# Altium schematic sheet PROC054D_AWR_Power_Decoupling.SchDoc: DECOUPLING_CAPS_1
size 558 x 431 mm; Date: Not shown in title block; ApprovedBy: Not shown in title block; CheckedBy: Not shown in title block; Author: Not shown in title block; CompanyName: Not shown in title block; DrawnBy: a0271760; Engineer: Not shown in title block; Organization: Not shown in title block; Address1: Not shown in title block; Address2: Not shown in title block; Address3: Not shown in title block; Address4: Not shown in title block; DocumentNumber: 11; Revision: Use project pAWRameter SCH_Rev; SheetNumber: 11; SheetTotal: 19; PageSetup: Record=PageOptions¦CenterHorizontal=True¦CenterVertical=True¦PrintScale=1.00¦XCorrection=1.00¦YCorrection=1.00¦PrintKind=0¦BorderSize=5000000¦LeftOffset=0¦BottomOffset=0¦Orientation=2¦PaperLength=1000¦PaperWidth=1000¦Scale=100¦PaperSource=15¦PrintQuality=600¦MediaType=1¦DitherType=10¦PaperKind=Letter¦PrintScaleMode=1
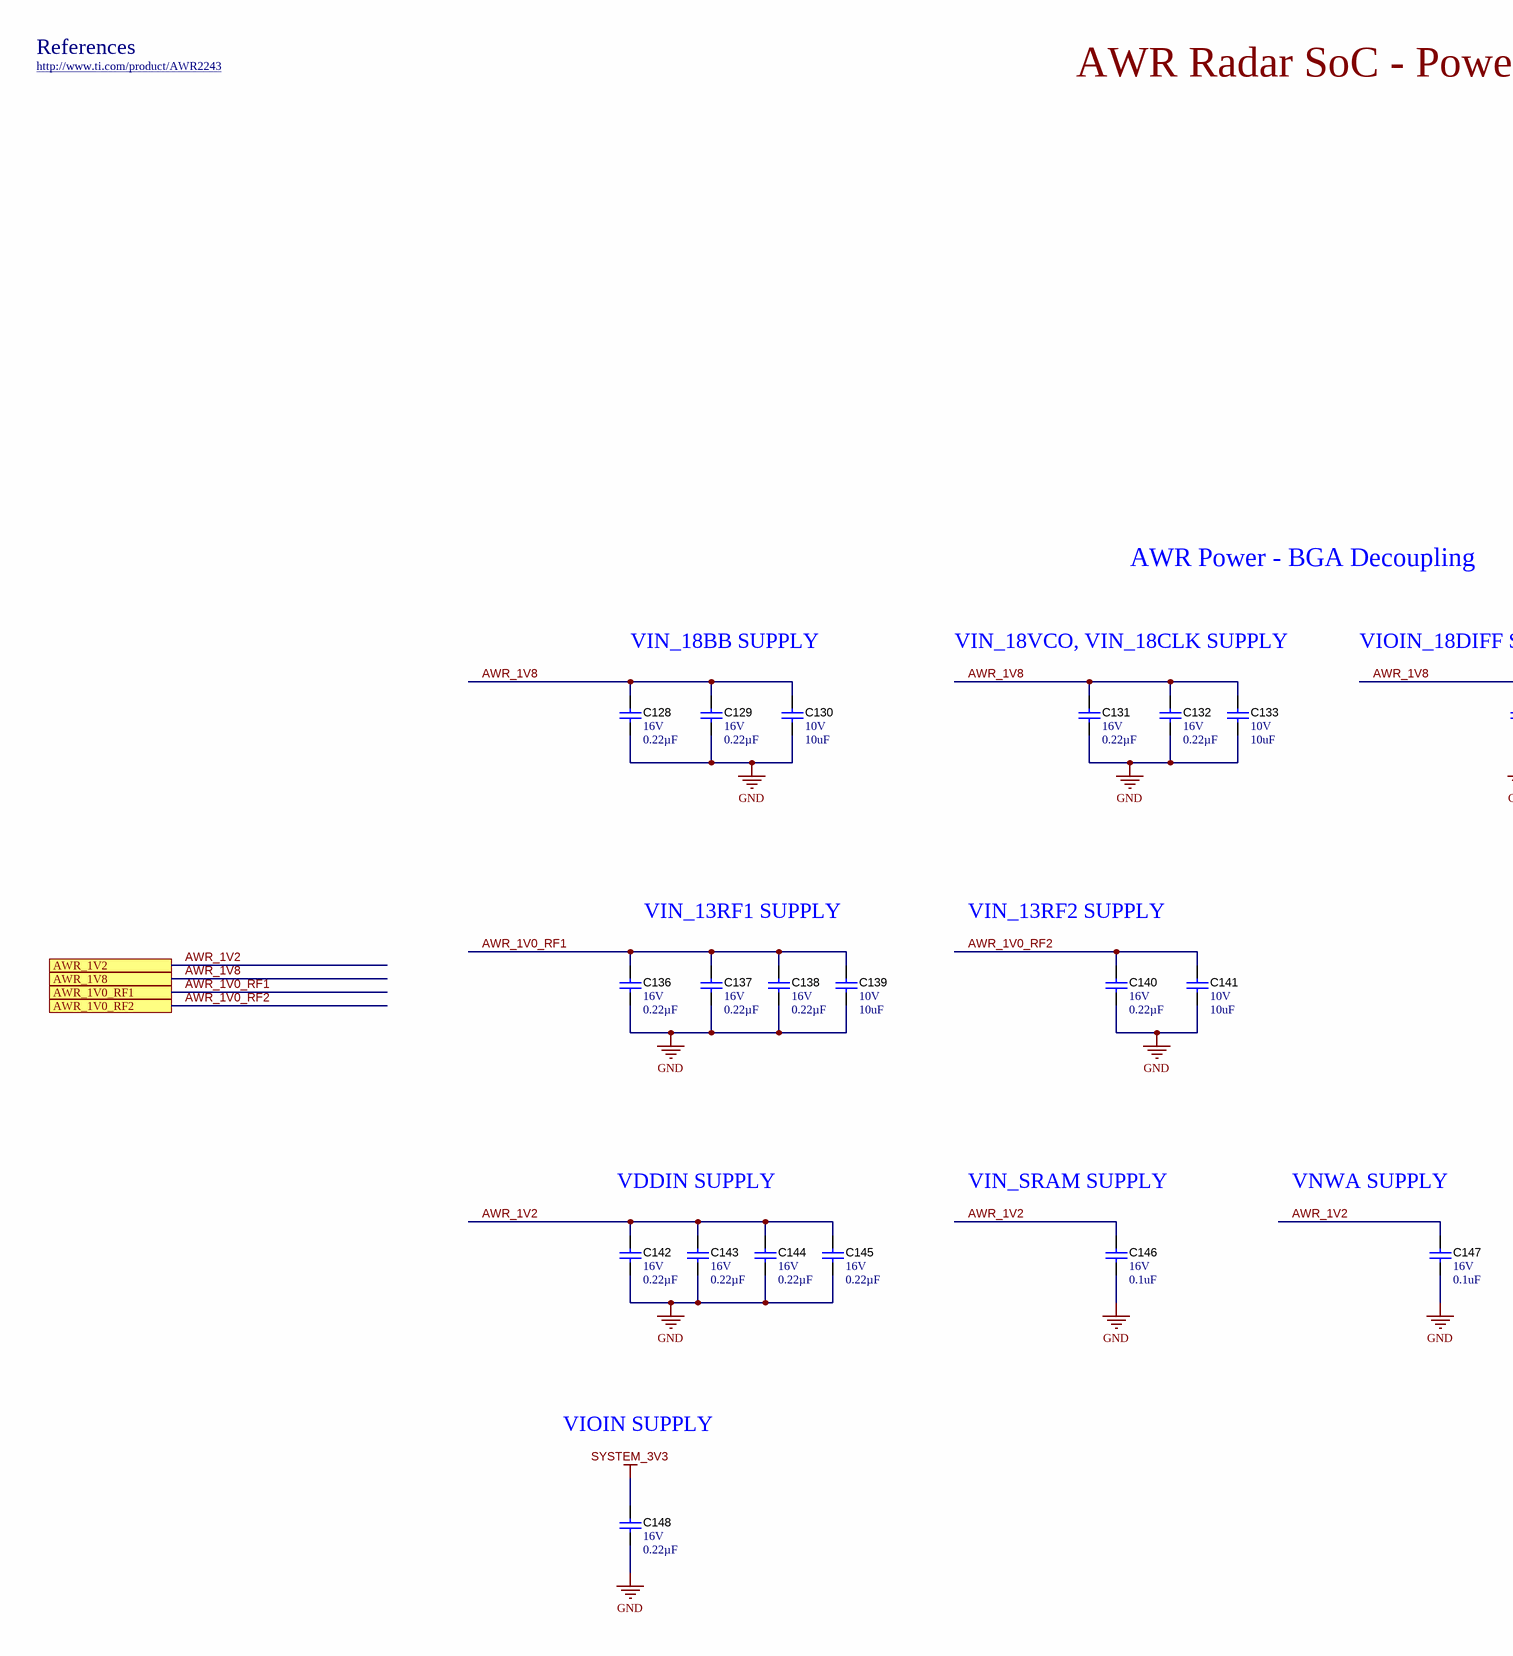
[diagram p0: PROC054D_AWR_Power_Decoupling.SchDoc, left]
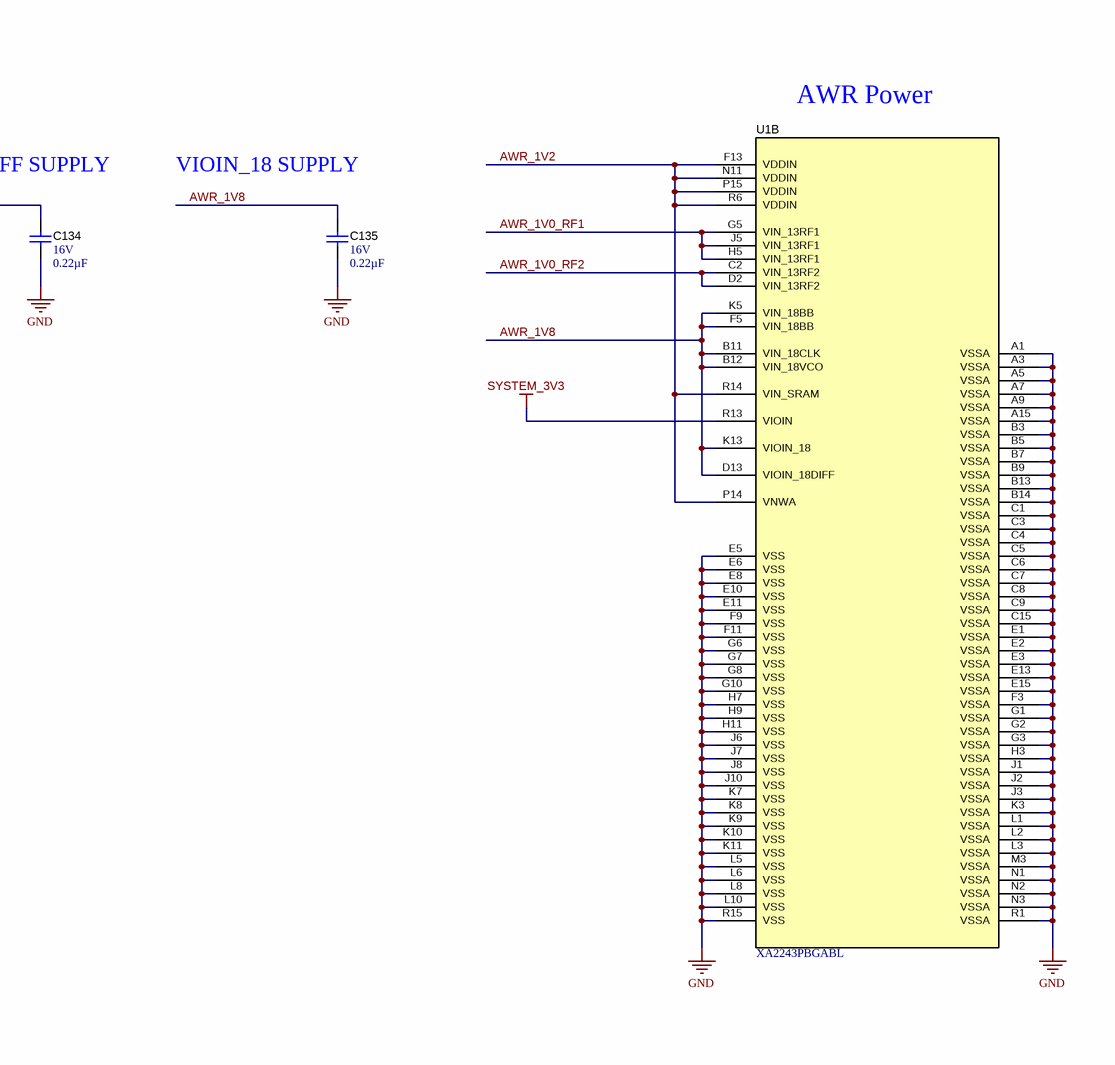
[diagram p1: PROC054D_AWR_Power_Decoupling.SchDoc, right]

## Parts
C128  VDC_V: 16V  ValueDisplayed: 0.22µF  [0402S]  (hidden comment: GCM155R71C224KE02D)
C129  VDC_V: 16V  ValueDisplayed: 0.22µF  [0402S]  (hidden comment: GCM155R71C224KE02D)
C130  VDC_V: 10V  ValueDisplayed: 10uF  [0805L]  (hidden comment: GCM21BR71A106KE22L)
C131  VDC_V: 16V  ValueDisplayed: 0.22µF  [0402S]  (hidden comment: GCM155R71C224KE02D)
C132  VDC_V: 16V  ValueDisplayed: 0.22µF  [0402S]  (hidden comment: GCM155R71C224KE02D)
C133  VDC_V: 10V  ValueDisplayed: 10uF  [0805L]  (hidden comment: GCM21BR71A106KE22L)
C134  VDC_V: 16V  ValueDisplayed: 0.22µF  [0402S]  (hidden comment: GCM155R71C224KE02D)
C135  VDC_V: 16V  ValueDisplayed: 0.22µF  [0402S]  (hidden comment: GCM155R71C224KE02D)
C136  VDC_V: 16V  ValueDisplayed: 0.22µF  [0402S]  (hidden comment: GCM155R71C224KE02D)
C137  VDC_V: 16V  ValueDisplayed: 0.22µF  [0402S]  (hidden comment: GCM155R71C224KE02D)
C138  VDC_V: 16V  ValueDisplayed: 0.22µF  [0402S]  (hidden comment: GCM155R71C224KE02D)
C139  VDC_V: 10V  ValueDisplayed: 10uF  [0805L]  (hidden comment: GCM21BR71A106KE22L)
C140  VDC_V: 16V  ValueDisplayed: 0.22µF  [0402S]  (hidden comment: GCM155R71C224KE02D)
C141  VDC_V: 10V  ValueDisplayed: 10uF  [0805L]  (hidden comment: GCM21BR71A106KE22L)
C142  VDC_V: 16V  ValueDisplayed: 0.22µF  [0402S]  (hidden comment: GCM155R71C224KE02D)
C143  VDC_V: 16V  ValueDisplayed: 0.22µF  [0402S]  (hidden comment: GCM155R71C224KE02D)
C144  VDC_V: 16V  ValueDisplayed: 0.22µF  [0402S]  (hidden comment: GCM155R71C224KE02D)
C145  VDC_V: 16V  ValueDisplayed: 0.22µF  [0402S]  (hidden comment: GCM155R71C224KE02D)
C146  VDC_V: 16V  ValueDisplayed: 0.1uF  [0402S]  (hidden comment: GCM155R71C104KA55D)
C147  VDC_V: 16V  ValueDisplayed: 0.1uF  [0402S]  (hidden comment: GCM155R71C104KA55D)
C148  VDC_V: 16V  ValueDisplayed: 0.22µF  [0402S]  (hidden comment: GCM155R71C224KE02D)
U1  XA2243PBGABL  [ABL0161A]  (part B of 2)

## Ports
AWR_1V0_RF1, AWR_1V0_RF2, AWR_1V2, AWR_1V8

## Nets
GND: C128.2 C129.2 C130.2 C131.2 C132.2 C133.2 C134.2 C135.2 C136.2 C137.2 C138.2 C139.2 C140.2 C141.2 C142.2 C143.2 C144.2 C145.2 C146.2 C147.2 C148.2 U1.A1(VSSA) U1.A3(VSSA) U1.A5(VSSA) U1.A7(VSSA) U1.A9(VSSA) U1.A15(VSSA) U1.B3(VSSA) U1.B5(VSSA) U1.B7(VSSA) U1.B9(VSSA) U1.B13(VSSA) U1.B14(VSSA) U1.C1(VSSA) U1.C3(VSSA) U1.C4(VSSA) U1.C5(VSSA) U1.C6(VSSA) U1.C7(VSSA) U1.C8(VSSA) U1.C9(VSSA) U1.C15(VSSA) U1.E1(VSSA) U1.E2(VSSA) U1.E3(VSSA) U1.E5(VSS) U1.E6(VSS) U1.E8(VSS) U1.E10(VSS) U1.E11(VSS) U1.E13(VSSA) U1.E15(VSSA) U1.F3(VSSA) U1.F9(VSS) U1.F11(VSS) U1.G1(VSSA) U1.G2(VSSA) U1.G3(VSSA) U1.G6(VSS) U1.G7(VSS) U1.G8(VSS) U1.G10(VSS) U1.H3(VSSA) U1.H7(VSS) U1.H9(VSS) U1.H11(VSS) U1.J1(VSSA) U1.J2(VSSA) U1.J3(VSSA) U1.J6(VSS) U1.J7(VSS) U1.J8(VSS) U1.J10(VSS) U1.K3(VSSA) U1.K7(VSS) U1.K8(VSS) U1.K9(VSS) U1.K10(VSS) U1.K11(VSS) U1.L1(VSSA) U1.L2(VSSA) U1.L3(VSSA) U1.L5(VSS) U1.L6(VSS) U1.L8(VSS) U1.L10(VSS) U1.M3(VSSA) U1.N1(VSSA) U1.N2(VSSA) U1.N3(VSSA) U1.R1(VSSA) U1.R15(VSS)
SYSTEM_3V3: C148.1 U1.R13(VIOIN)
AWR_1V0_RF1: C136.1 C137.1 C138.1 C139.1 U1.G5(VIN_13RF1) U1.H5(VIN_13RF1) U1.J5(VIN_13RF1) ; port AWR_1V0_RF1
AWR_1V0_RF2: C140.1 C141.1 U1.C2(VIN_13RF2) U1.D2(VIN_13RF2) ; port AWR_1V0_RF2
AWR_1V2: C142.1 C143.1 C144.1 C145.1 C146.1 C147.1 U1.F13(VDDIN) U1.N11(VDDIN) U1.P14(VNWA) U1.P15(VDDIN) U1.R6(VDDIN) U1.R14(VIN_SRAM) ; port AWR_1V2
AWR_1V8: C128.1 C129.1 C130.1 C131.1 C132.1 C133.1 C134.1 C135.1 U1.B11(VIN_18CLK) U1.B12(VIN_18VCO) U1.D13(VIOIN_18DIFF) U1.F5(VIN_18BB) U1.K5(VIN_18BB) U1.K13(VIOIN_18) ; port AWR_1V8

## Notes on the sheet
- References
- http://www.ti.com/product/AWR2243
- AWR Radar SoC - Power and Decoupling
- AWR Power - BGA Decoupling
- AWR Power
- VIN_18BB SUPPLY
- VIN_18VCO, VIN_18CLK SUPPLY
- VIOIN_18DIFF SUPPLY
- VIOIN_18 SUPPLY
- VIN_13RF1 SUPPLY
- VIN_13RF2 SUPPLY
- VDDIN SUPPLY
- VIN_SRAM SUPPLY
- VNWA SUPPLY
- VIOIN SUPPLY

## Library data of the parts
C128 C129 C131 C132 C134-C138 C140 C142-C145 C148 = CMP-0078265-1: CAP, CERM, 0.22 µF, 16 V,+/- 10%, X7R, AEC-Q200 Grade 1, 0402; Manufacturer: MuRata; TaMin_C: -55°C; Polarized: N; SizeAreaWB_mm2: 3; U/M: EA; Value: 0.22uF; TaMax_C: 125°C; SizeZ_mm: 0.6; SizeX_mm: 1; SizeY_mm: 0.5; Cap_Case: 0402; CompType: Capacitor; AEC Qualified: Y; Cap_F: 220nF; AEC Category: Q200
C130 C133 C139 C141 = CMP-0008017-2: CAP, CERM, 10 uF, 10 V, +/- 10%, X7R, 0805; Manufacturer: MuRata; TaMin_C: -55°C; Polarized: N; SizeAreaWB_mm2: 6.75; Value1: Unknown; U/M: EA; Value: 10uF; TaMax_C: 125°C; SizeZ_mm: 1.45; SizeX_mm: 2; SizeY_mm: 1.25; Cap_Case: 0805; SizeArea_mm2: 2.5; CompType: Capacitor; Cap_F: 10µF; AEC Category: Q200
C146 C147 = CMP-0006351-2: CAP, CERM, 0.1 uF, 16 V, +/- 10%, X7R, 0402; Manufacturer: MuRata; TaMin_C: -55°C; Polarized: N; SizeAreaWB_mm2: 3; Value1: Unknown; U/M: EA; Value: 0.1uF; TaMax_C: 125°C; SizeZ_mm: 0.6; SizeX_mm: 1; SizeY_mm: 0.5; Cap_Case: 0402; Cap_F: 100nF; AEC Category: Q200
U1 = CMP-0082537-1: Single Chip 77 and 79 GHz FMCW Transceiver, ABL0161A (FCBGA-161); Alternate Manufacturer: Texas Instruments; SizeAreaWB_mm2: 153.76; Rating: Automotive; SizeZ_mm: 1.17; SizeX_mm: 10.4; SizeArea_mm2: 108.16; CompType: IC; AEC Qualified: Y; AEC Category: Q200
